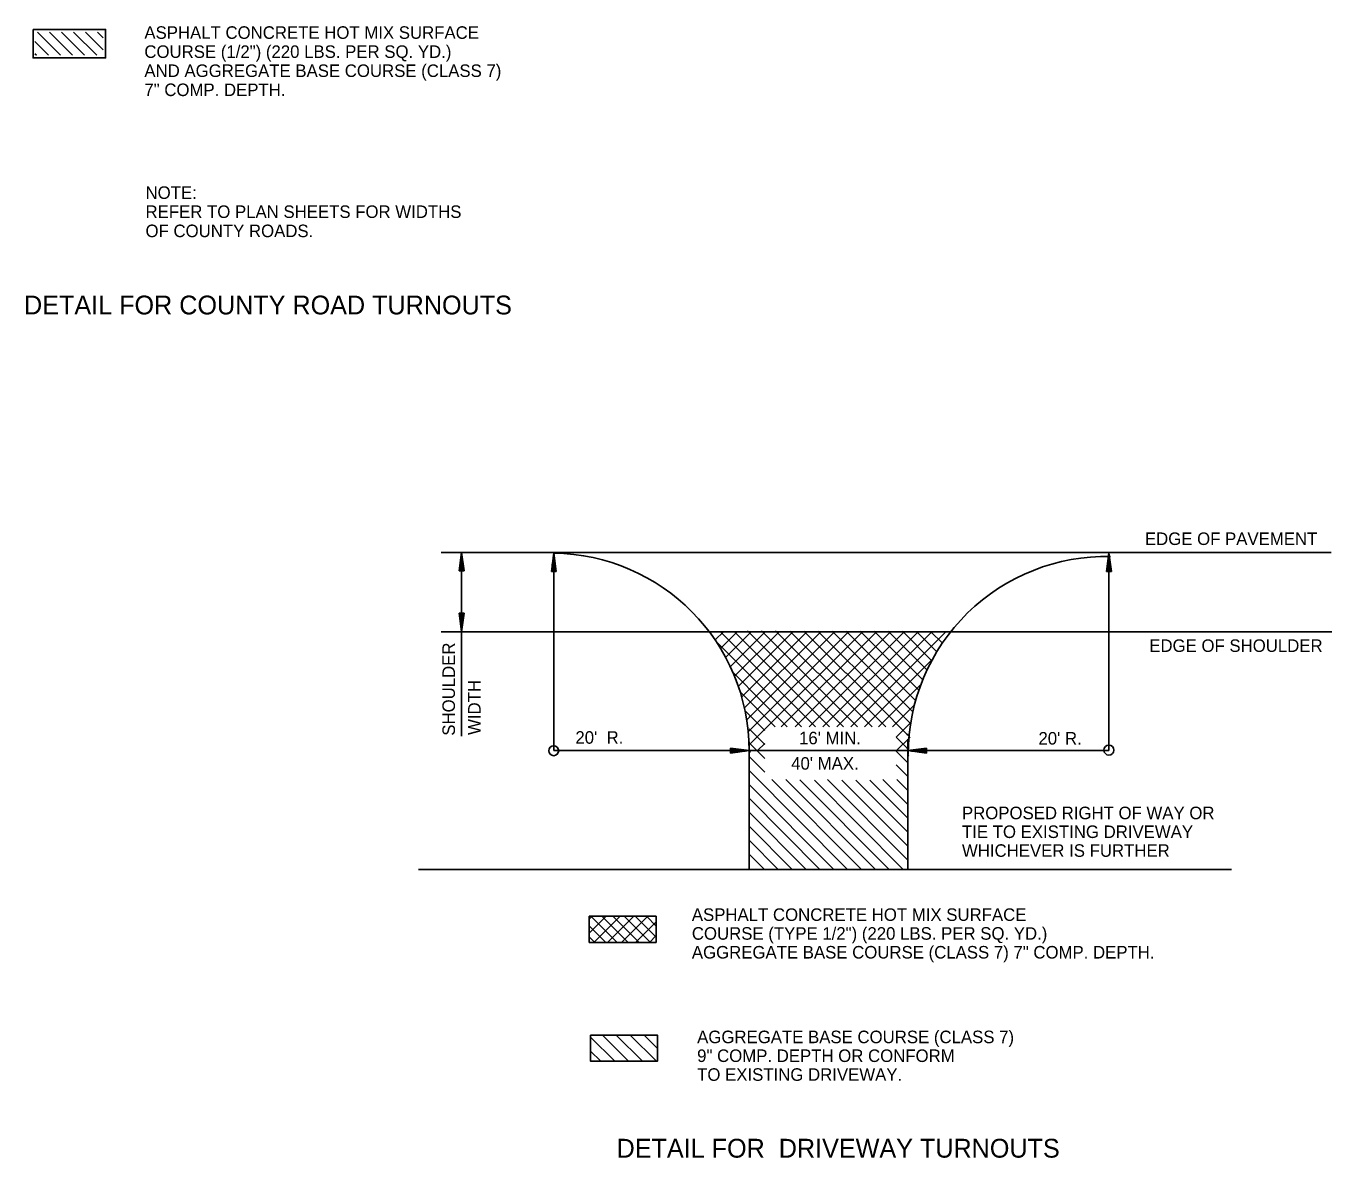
# Model space of a CAD drawing. Extents: x 836 to 5683, y -463 to 1545.
# Drawn here: x 1043 to 1667, y 162 to 704 of the extents above; entities that cross this region are included whole.
import ezdxf

# ---------------------------------------------------------------- set-up
doc = ezdxf.new("R2010")
doc.units = 0
for name, color, linetype in [('R_Border', 7, 'Continuous'), ('R_Draft', 7, 'Continuous'), ('R_Grid', 7, 'Continuous'), ('STAMP_PP', 7, 'Continuous')]:
    doc.layers.add(name, color=color, linetype=linetype)

msp = doc.modelspace()

# ---------------------------------------------------------------- linework, layer by layer
at = {"layer": 'R_Draft'}
for p, q in [((1421.82, 394.24), (1447.52, 368.36)), ((1435.15, 394.18), (1465.19, 363.97)), ((1384.42, 385.06), (1401.12, 368.36)), ((1453.62, 382.27), (1465.93, 369.9)), ((1386.82, 376), (1396.22, 366.6)), ((1395.14, 380.22), (1407, 368.36)), ((1388.7, 367.45), (1396.22, 359.93)), ((1459.04, 363.46), (1464.68, 357.87)), ((1464.68, 362.43), (1464.68, 357.02)), ((1388.7, 361.12), (1388.7, 356.68)), ((1388.7, 360.78), (1396.22, 353.26)), ((1459.04, 356.79), (1464.68, 351.21)), ((1388.7, 354.11), (1396.22, 346.65)), ((1459.04, 350.12), (1464.68, 344.54)), ((1388.7, 347.44), (1435.84, 300.13)), ((1388.7, 340.77), (1429.23, 300.13)), ((1399.59, 343.23), (1442.51, 300.13)), ((1406.25, 343.23), (1449.18, 300.13)), ((1413.04, 343), (1455.79, 300.13)), ((1419.93, 342.77), (1462.46, 300.13)), ((1426.15, 343.23), (1464.68, 304.58)), ((1433.1, 342.88), (1464.68, 311.25)), ((1439.77, 342.88), (1464.68, 317.92)), ((1446.44, 342.83), (1464.68, 324.59)), ((1452.71, 343.23), (1464.68, 331.26)), ((1459.32, 343.23), (1464.68, 337.87)), ((1388.7, 334.16), (1422.61, 300.13)), ((1388.7, 327.49), (1415.94, 300.13)), ((1388.7, 320.82), (1409.33, 300.13)), ((1388.7, 314.16), (1402.66, 300.13)), ((1388.7, 307.49), (1396.05, 300.13))]:
    msp.add_line(p, q, dxfattribs=at)
for points in [[(1048.3, 700.79), (1059.36, 689.67)], [(1054, 700.79), (1065.11, 689.67)], [(1059.76, 700.79), (1070.87, 689.67)], [(1065.57, 700.79), (1076.63, 689.67)], [(1071.33, 700.79), (1079.76, 692.29)], [(1077.03, 700.79), (1079.76, 698.05)], [(1047.05, 696.23), (1053.6, 689.67)], [(1047.05, 690.41), (1047.84, 689.67)], [(1372.45, 409.92), (1376.44, 413.85)], [(1375.02, 413.85), (1420.45, 368.36)], [(1375.08, 405.87), (1383.06, 413.85)], [(1377.47, 401.59), (1389.72, 413.85)], [(1379.75, 397.2), (1396.39, 413.85)], [(1381.69, 413.85), (1427.23, 368.36)], [(1381.74, 392.59), (1403.06, 413.85)], [(1383.57, 387.74), (1409.67, 413.85)], [(1385.16, 382.73), (1416.34, 413.85)], [(1386.48, 377.37), (1423.01, 413.85)], [(1387.56, 371.78), (1429.62, 413.85)], [(1387.96, 414.3), (1433.9, 368.36)], [(1388.3, 365.91), (1436.29, 413.85)], [(1394.68, 414.25), (1440.63, 368.36)], [(1397.42, 368.36), (1442.96, 413.85)], [(1401.41, 414.25), (1421.59, 394.01)], [(1404.09, 368.36), (1449.63, 413.85)], [(1408.19, 414.19), (1454.08, 368.36)], [(1410.76, 368.36), (1456.3, 413.85)], [(1414.92, 414.19), (1435.04, 394.01)], [(1417.37, 368.36), (1462.91, 413.85)], [(1421.64, 414.19), (1453.62, 382.27)], [(1424.04, 368.36), (1469.58, 413.85)], [(1428.37, 414.13), (1448.49, 394.01)], [(1430.71, 368.36), (1476.19, 413.85)], [(1435.1, 414.13), (1468.38, 380.9)], [(1437.38, 368.36), (1482.86, 413.85)], [(1441.88, 414.08), (1469.98, 385.98)], [(1448.55, 414.08), (1471.8, 390.88)], [(1455.27, 414.08), (1473.86, 395.55)], [(1462.06, 414.08), (1476.14, 400)], [(1468.84, 414.02), (1478.53, 404.27)], [(1475.68, 413.85), (1481.15, 408.32)], [(1372.97, 409.12), (1413.72, 368.36)], [(1443.99, 368.36), (1476.59, 400.91)], [(1380.95, 394.47), (1395.14, 380.22)], [(1448.49, 394.01), (1467.02, 375.49)], [(1450.66, 368.36), (1470.89, 388.6)], [(1457.33, 368.36), (1467.81, 378.85)], [(1388.7, 373.26), (1388.93, 373.09)], [(1459.04, 363.46), (1466.05, 370.41)], [(1464.17, 371.73), (1464.68, 371.16)], [(1388.7, 359.7), (1397.42, 368.36)], [(1388.7, 366.6), (1388.87, 366.37)], [(1459.21, 356.96), (1465.71, 363.46)], [(1464.17, 364.89), (1464.91, 364.14)], [(1388.7, 359.87), (1388.81, 359.7)], [(1388.81, 356.62), (1389.33, 356.16)], [(1392.69, 356.96), (1396.22, 360.44)], [(1464.17, 358.16), (1464.68, 357.7)], [(1464.45, 354.8), (1465.08, 354.28)], [(1312.26, 276.31), (1313.69, 277.73)], [(1312.26, 269.7), (1320.3, 277.73)], [(1312.95, 277.73), (1325.54, 265.19)], [(1314.43, 265.19), (1326.97, 277.73)], [(1318.3, 277.73), (1330.84, 265.19)], [(1321.04, 265.19), (1333.58, 277.73)], [(1323.6, 277.73), (1336.14, 265.19)], [(1327.71, 265.19), (1340.25, 277.73)], [(1328.96, 277.73), (1341.5, 265.19)], [(1334.26, 277.73), (1344.24, 267.76)], [(1334.38, 265.19), (1344.24, 275.11)], [(1339.56, 277.73), (1344.24, 273.06)], [(1312.26, 273.12), (1320.18, 265.19)], [(1312.26, 267.81), (1314.88, 265.19)], [(1340.99, 265.19), (1344.24, 268.44)], [(1312.89, 219.88), (1324.46, 208.31)], [(1318.53, 220.85), (1331.07, 208.31)], [(1325.2, 220.85), (1337.74, 208.31)], [(1331.87, 220.85), (1344.41, 208.31)], [(1338.48, 220.85), (1344.87, 214.46)], [(1312.89, 213.21), (1317.79, 208.31)]]:
    msp.add_lwpolyline(points, dxfattribs=at)
at = {"layer": 'R_Grid'}
for p, q in [((1250.07, 442.99), (1251.21, 451.81)), ((1250.99, 442.98), (1250.99, 450.02)), ((1251.21, 413.85), (1251.21, 451.81)), ((1251.21, 451.81), (1251.21, 442.99)), ((1252.36, 442.99), (1251.21, 451.81)), ((1251.44, 442.99), (1251.44, 450.02)), ((1294.14, 442.64), (1295.28, 451.47)), ((1295.28, 356.96), (1295.28, 451.47)), ((1295.28, 451.47), (1295.28, 442.64)), ((1296.43, 442.65), (1295.28, 451.47)), ((1559.7, 442.76), (1560.84, 451.58)), ((1560.62, 442.76), (1560.61, 449.79)), ((1560.84, 356.96), (1560.84, 451.58)), ((1560.84, 451.58), (1560.84, 442.76)), ((1561.99, 442.76), (1560.84, 451.58)), ((1561.07, 442.76), (1561.07, 449.79)), ((1250.3, 442.98), (1250.3, 444.72)), ((1250.53, 442.98), (1250.53, 446.5)), ((1250.76, 442.98), (1250.76, 448.29)), ((1251.67, 442.98), (1251.67, 448.29)), ((1251.91, 442.99), (1251.9, 446.51)), ((1252.14, 442.99), (1252.13, 444.72)), ((1294.36, 442.64), (1294.36, 444.37)), ((1294.59, 442.64), (1294.59, 446.16)), ((1294.82, 442.64), (1294.82, 447.95)), ((1295.06, 442.64), (1295.05, 449.68)), ((1295.5, 442.65), (1295.5, 449.68)), ((1295.73, 442.64), (1295.73, 447.95)), ((1295.97, 442.65), (1295.96, 446.17)), ((1296.2, 442.64), (1296.19, 444.38)), ((1559.92, 442.76), (1559.92, 444.49)), ((1560.16, 442.75), (1560.15, 446.28)), ((1560.38, 442.75), (1560.38, 448.06)), ((1561.3, 442.76), (1561.29, 448.06)), ((1561.53, 442.76), (1561.53, 446.28)), ((1561.76, 442.76), (1561.75, 444.49)), ((1252.36, 442.99), (1250.07, 442.99)), ((1296.43, 442.65), (1294.14, 442.64)), ((1561.99, 442.76), (1559.7, 442.76)), ((1250.07, 422.67), (1251.21, 413.85)), ((1250.07, 422.67), (1252.36, 422.67)), ((1250.29, 422.67), (1250.3, 420.94)), ((1250.52, 422.67), (1250.53, 419.15)), ((1250.76, 422.67), (1250.76, 417.37)), ((1250.99, 422.67), (1250.99, 415.64)), ((1251.21, 413.85), (1251.21, 422.67)), ((1252.36, 422.67), (1251.21, 413.85)), ((1251.44, 422.67), (1251.44, 415.64)), ((1251.67, 422.68), (1251.67, 417.37)), ((1251.9, 422.68), (1251.9, 419.15)), ((1252.13, 422.67), (1252.13, 420.94)), ((1251.21, 363.85), (1251.21, 413.85)), ((1388.7, 356.96), (1295.28, 356.96)), ((1379.87, 358.1), (1388.7, 356.96)), ((1379.88, 355.81), (1379.87, 358.1)), ((1379.87, 357.88), (1381.6, 357.88)), ((1379.87, 357.64), (1383.39, 357.65)), ((1379.87, 357.42), (1385.18, 357.42)), ((1379.87, 357.18), (1386.91, 357.19)), ((1379.87, 356.5), (1385.18, 356.51)), ((1379.87, 356.04), (1381.61, 356.05)), ((1388.7, 356.96), (1379.88, 356.96)), ((1379.88, 355.81), (1388.7, 356.96)), ((1379.88, 356.73), (1386.91, 356.73)), ((1379.88, 356.27), (1383.4, 356.27)), ((1388.7, 356.96), (1464.68, 356.96)), ((1473.5, 358.11), (1464.68, 356.96)), ((1464.68, 356.96), (1560.84, 356.96)), ((1464.68, 356.96), (1473.5, 356.96)), ((1473.5, 355.82), (1464.68, 356.96)), ((1473.5, 357.19), (1466.47, 357.19)), ((1473.51, 356.74), (1466.47, 356.74)), ((1473.51, 357.42), (1468.2, 357.41)), ((1473.51, 356.5), (1468.2, 356.51)), ((1473.5, 357.65), (1469.98, 357.65)), ((1473.51, 356.28), (1469.99, 356.27)), ((1473.5, 357.88), (1471.77, 357.87)), ((1473.51, 356.05), (1471.77, 356.04)), ((1473.5, 358.11), (1473.5, 355.82))]:
    msp.add_line(p, q, dxfattribs=at)
for centre in [(1295.26, 356.93), (1560.81, 357.2)]:
    msp.add_circle(centre, 2.37, dxfattribs=at)
at = {"layer": 'STAMP_PP'}
for p, q in [((1241.41, 451.81), (1667.16, 451.81)), ((1241.41, 413.85), (1667.48, 413.85)), ((1388.7, 356.96), (1388.7, 300.13)), ((1464.68, 300.08), (1464.68, 357.19)), ((1230.58, 300.13), (1619.47, 300.13))]:
    msp.add_line(p, q, dxfattribs=at)
for points in [[(1046.19, 702.04), (1046.19, 688.42), (1080.9, 688.42), (1080.9, 702.04)], [(1312.26, 277.73), (1312.26, 265.19), (1344.24, 265.19), (1344.24, 277.73)], [(1312.89, 220.85), (1312.89, 208.31), (1344.87, 208.31), (1344.87, 220.85)]]:
    msp.add_lwpolyline(points, close=True, dxfattribs=at)
for centre, radius, start, end in [((1294.06, 356.81), 94.68, 0.07639, 89.27429), ((1559.5, 355.14), 94.72, 88.75379, 180)]:
    msp.add_arc(centre, radius, start, end, dxfattribs=at)

# ---------------------------------------------------------------- texts
at = {"layer": 'R_Border'}
for s, height, p in [('ASPHALT CONCRETE HOT MIX SURFACE', 6, (1099.45, 697.55)), ('COURSE (1/2") (220 LBS. PER SQ. YD.)', 6, (1099.45, 688.42)), ('AND AGGREGATE BASE COURSE (CLASS 7) ', 6, (1099.45, 679.29)), ('7" COMP. DEPTH.', 6, (1099.45, 670.16)), ('NOTE:', 6, (1100, 620.96)), ('REFER TO PLAN SHEETS FOR WIDTHS', 6, (1100, 611.84)), ('OF COUNTY ROADS.', 6, (1100, 602.66)), (' DETAIL FOR COUNTY ROAD TURNOUTS ', 9, (1038.55, 565.69)), ('EDGE OF PAVEMENT', 6, (1578.05, 455.36)), ('EDGE OF SHOULDER', 6, (1580.13, 404.2)), ("20'  R.", 6, (1305.62, 360.27)), ("16' MIN.", 6, (1412.59, 360)), ("20' R.", 6, (1527.12, 359.87)), ("40' MAX.", 6, (1408.84, 347.86)), ('PROPOSED RIGHT OF WAY OR', 6, (1490.53, 324.16)), ('TIE TO EXISTING DRIVEWAY', 6, (1490.53, 315.16)), ('WHICHEVER IS FURTHER', 6, (1490.53, 306.16)), ('ASPHALT CONCRETE HOT MIX SURFACE', 6, (1361.33, 275.5)), ('COURSE (TYPE 1/2") (220 LBS. PER SQ. YD.)', 6, (1361.33, 266.5)), ('AGGREGATE BASE COURSE (CLASS 7) 7" COMP. DEPTH.', 6, (1361.33, 257.5)), ('AGGREGATE BASE COURSE (CLASS 7)', 6, (1363.86, 216.99)), ('9" COMP. DEPTH OR CONFORM', 6, (1363.86, 207.99)), ('TO EXISTING DRIVEWAY.', 6, (1363.86, 198.99)), (' DETAIL FOR  DRIVEWAY TURNOUTS ', 9, (1321.99, 162.23))]:
    msp.add_text(s, height=height, dxfattribs=at).set_placement(p)
for s, p in [('SHOULDER', (1248.02, 364.12)), ('WIDTH', (1260.29, 364.48))]:
    msp.add_text(s, height=6, rotation=90, dxfattribs=at).set_placement(p)

doc.saveas('drawing.dxf')
